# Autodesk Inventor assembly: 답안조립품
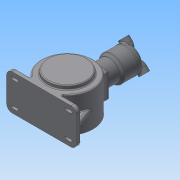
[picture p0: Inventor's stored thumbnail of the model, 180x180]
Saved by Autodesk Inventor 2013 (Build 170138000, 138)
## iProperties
Created: 2015-06
Part Number: 답안조립품
Document SubType Name: Assembly
Designer: Administrator
Author: Administrator
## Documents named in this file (15)
- C:\Users\Administrator\Desktop\450606V1019\답안조립품.iam
- C:\Users\Administrator\Desktop\450606V1019\본체.ipt
- C:\Users\Administrator\Desktop\450606V1019\M4x0.7.ipt
- C:\Users\Administrator\Desktop\450606V1019\M5x0.8.ipt
- C:\Users\Administrator\Desktop\450606V1019\메인 크랭크 축-구동부.ipt
- C:\Users\Administrator\Desktop\450606V1019\메인커버.ipt
- C:\Users\Administrator\Desktop\450606V1019\베어링 6204.ipt
- C:\Users\Administrator\Desktop\450606V1019\베어링 NA 4902.ipt
- C:\Users\Administrator\Desktop\450606V1019\실린더.ipt
- C:\Users\Administrator\Desktop\450606V1019\실린더헤드.ipt
- C:\Users\Administrator\Desktop\450606V1019\오일실.ipt
- C:\Users\Administrator\Desktop\450606V1019\커넥팅 로드.ipt
- C:\Users\Administrator\Desktop\450606V1019\크랭크 서브축.ipt
- C:\Users\Administrator\Desktop\450606V1019\피스톤 핀.ipt
- C:\Users\Administrator\Desktop\450606V1019\피스톤.ipt
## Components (14 placed, 4 different names)
1. 피스톤 핀:1 — 플러쉬:1
2. 피스톤:1 — 플러쉬:1
3. M4x0.7:1
4. M4x0.7:3
5. M4x0.7:4
6. M4x0.7:5
7. M4x0.7:7
8. M4x0.7:9
9. M4x0.7:10
10. M4x0.7:11
11. M5x0.8:1
12. M5x0.8:2
13. M5x0.8:3
14. M5x0.8:4
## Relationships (1: Flush 1)
- 플러쉬:1 [Flush]: 피스톤 핀:1 ↔ 피스톤:1
